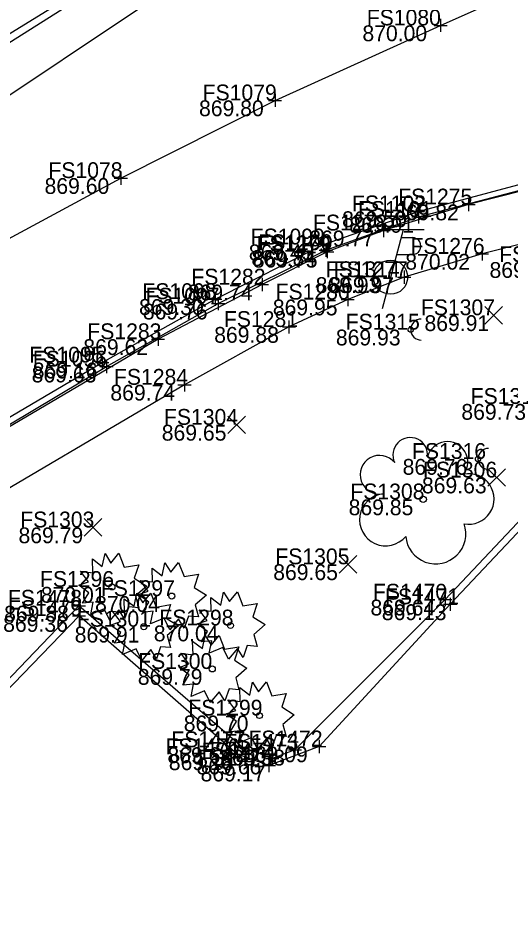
# Model space of a CAD drawing. Extents: x 1479420 to 1479833, y 379731 to 380103.
# Drawn here: x 1479485.7 to 1479523.1, y 379796.9 to 379864.3 of the extents above; entities that cross this region are included whole.
import ezdxf

# ---------------------------------------------------------------- set-up
doc = ezdxf.new("R2010")
doc.units = 0
for name, color, linetype in [('PV_X_COP', 7, 'Continuous'), ('PV_X_Curb', 7, 'Continuous'), ('PV_X_Walk', 7, 'Continuous'), ('SV_X_Random_Point', 7, 'Continuous'), ('SV_X_Shot_Marker', 7, 'Continuous'), ('SV_X_Text_Elevation', 7, 'Continuous'), ('SV_X_Text_Name', 7, 'Continuous'), ('UT_X_Misc_Cells', 7, 'Continuous'), ('UT_X_Water', 7, 'Continuous'), ('VG_X_Cells', 7, 'Continuous')]:
    doc.layers.add(name, color=color, linetype=linetype)

msp = doc.modelspace()

# ---------------------------------------------------------------- linework, layer by layer
at = {"layer": 'PV_X_COP'}
msp.add_lwpolyline([(1479441.789, 379822.02), (1479455.003, 379829.684), (1479469.105, 379838.412), (1479482.144, 379845.998), (1479493.535, 379852.152), (1479505.235, 379858.045), (1479517.8, 379863.732), (1479530.742, 379869.52), (1479544.647, 379875.382), (1479558.927, 379881.46), (1479574.038, 379887.901), (1479589.196, 379894.596), (1479596.439, 379897.36)], dxfattribs=at)
at = {"layer": 'PV_X_Curb'}
for points in [[(1479566.948, 379909.055), (1479563.851, 379905.522), (1479559.694, 379902.148), (1479555.354, 379899.307), (1479545.42, 379894.598), (1479534.9, 379889.656), (1479522.397, 379883.596), (1479509.98, 379877.664), (1479501.207, 379872.624), (1479492.667, 379867.773), (1479483.86, 379862.333), (1479467.175, 379851.843), (1479450.132, 379841.187), (1479435.273, 379831.857)], [(1479567.166, 379908.643), (1479563.944, 379905.002), (1479559.953, 379901.759), (1479555.611, 379898.812), (1479545.712, 379894.104), (1479535.142, 379889.114), (1479522.804, 379883.209), (1479510.321, 379877.208), (1479501.52, 379872.223), (1479492.734, 379867.269), (1479484.26, 379861.901), (1479467.4, 379851.399), (1479450.552, 379840.846), (1479435.368, 379831.409)], [(1479448.263, 379811.446), (1479461.223, 379819.505), (1479478.3, 379830.094), (1479484.788, 379833.845), (1479492.119, 379838.16), (1479500.701, 379842.975), (1479508.918, 379847.117), (1479516.087, 379849.63), (1479529.031, 379853.073), (1479547.645, 379857.816), (1479566.743, 379862.68), (1479585.84, 379867.633), (1479595.941, 379870.21)], [(1479448.497, 379810.926), (1479461.699, 379819.081), (1479478.683, 379829.765), (1479485.034, 379833.446), (1479492.452, 379837.857), (1479500.924, 379842.633), (1479509.095, 379846.687), (1479516.116, 379849.207), (1479529.309, 379852.683), (1479547.62, 379857.329), (1479567.188, 379862.296), (1479585.958, 379867.104), (1479596.074, 379869.8)], [(1479601.319, 379856.891), (1479590.521, 379858.038), (1479580.718, 379858.057), (1479571.147, 379856.791), (1479561.287, 379853.753), (1479553.092, 379850.702), (1479544.73, 379845.631), (1479537.421, 379839.852), (1479530.35, 379833.145), (1479518.148, 379820.183), (1479506.748, 379808.804), (1479505.037, 379808.132), (1479502.743, 379808.986), (1479490.356, 379819.723), (1479452.909, 379780.6)], [(1479601.347, 379856.369), (1479590.364, 379857.442), (1479580.925, 379857.48), (1479571.059, 379856.275), (1479561.558, 379853.273), (1479553.285, 379850.192), (1479545.205, 379845.234), (1479537.871, 379839.395), (1479530.786, 379832.841), (1479518.522, 379819.829), (1479508.592, 379809.053), (1479504.774, 379807.6), (1479502.376, 379808.454), (1479490.367, 379818.943), (1479453.507, 379780.799)]]:
    msp.add_lwpolyline(points, dxfattribs=at)
at = {"layer": 'PV_X_Walk'}
for points in [[(1479600.533, 379870.638), (1479580.734, 379865.6), (1479561.549, 379860.766), (1479542.709, 379855.919), (1479519.925, 379850.15), (1479513.475, 379848.178), (1479509.191, 379846.567), (1479504.249, 379844.075), (1479496.362, 379839.934), (1479478.251, 379829.275), (1479450.128, 379811.818)], [(1479601.313, 379866.859), (1479581.547, 379861.918), (1479562.5, 379857.02), (1479543.703, 379852.153), (1479520.939, 379846.407), (1479515.035, 379844.633), (1479510.748, 379842.941), (1479506.291, 379840.861), (1479498.375, 379836.477), (1479480.408, 379825.918), (1479452.204, 379808.527)]]:
    msp.add_lwpolyline(points, dxfattribs=at)
at = {"layer": 'SV_X_Random_Point'}
for p, q in [((1479521.152, 379841.083), (1479522.486, 379842.418)), ((1479521.152, 379842.418), (1479522.486, 379841.083)), ((1479501.654, 379832.774), (1479502.988, 379834.109)), ((1479501.654, 379834.109), (1479502.988, 379832.774)), ((1479521.393, 379828.776), (1479522.727, 379830.111)), ((1479521.393, 379830.111), (1479522.727, 379828.776)), ((1479490.759, 379824.993), (1479492.093, 379826.328)), ((1479490.759, 379826.328), (1479492.093, 379824.993)), ((1479510.111, 379822.197), (1479511.445, 379823.532)), ((1479510.111, 379823.532), (1479511.445, 379822.197))]:
    msp.add_line(p, q, dxfattribs=at)
at = {"layer": 'SV_X_Shot_Marker'}
for p, q in [((1479517.3, 379863.732), (1479518.3, 379863.732)), ((1479517.8, 379864.232), (1479517.8, 379863.232)), ((1479517.8, 379863.732), (1479517.8, 379863.732)), ((1479505.235, 379858.545), (1479505.235, 379857.545)), ((1479504.735, 379858.045), (1479505.735, 379858.045)), ((1479505.235, 379858.045), (1479505.235, 379858.045)), ((1479493.535, 379852.652), (1479493.535, 379851.652)), ((1479493.035, 379852.152), (1479494.035, 379852.152)), ((1479493.535, 379852.152), (1479493.535, 379852.152)), ((1479519.925, 379850.65), (1479519.925, 379849.65)), ((1479515.587, 379849.63), (1479516.587, 379849.63)), ((1479516.087, 379850.13), (1479516.087, 379849.13)), ((1479516.087, 379849.63), (1479516.087, 379849.63)), ((1479516.116, 379849.707), (1479516.116, 379848.707)), ((1479519.425, 379850.15), (1479520.425, 379850.15)), ((1479519.925, 379850.15), (1479519.925, 379850.15)), ((1479515.616, 379849.207), (1479516.616, 379849.207)), ((1479516.116, 379849.207), (1479516.116, 379849.207)), ((1479513.475, 379848.678), (1479513.475, 379847.678)), ((1479508.918, 379847.617), (1479508.918, 379846.617)), ((1479512.975, 379848.178), (1479513.975, 379848.178)), ((1479513.475, 379848.178), (1479513.475, 379848.178)), ((1479508.418, 379847.117), (1479509.418, 379847.117)), ((1479508.918, 379847.117), (1479508.918, 379847.117)), ((1479509.095, 379847.187), (1479509.095, 379846.187)), ((1479509.191, 379847.067), (1479509.191, 379846.067)), ((1479520.939, 379846.907), (1479520.939, 379845.907)), ((1479508.595, 379846.687), (1479509.595, 379846.687)), ((1479508.691, 379846.567), (1479509.691, 379846.567)), ((1479509.095, 379846.687), (1479509.095, 379846.687)), ((1479509.191, 379846.567), (1479509.191, 379846.567)), ((1479520.439, 379846.407), (1479521.439, 379846.407)), ((1479520.939, 379846.407), (1479520.939, 379846.407)), ((1479515.035, 379845.133), (1479515.035, 379844.133)), ((1479504.249, 379844.575), (1479504.249, 379843.575)), ((1479514.535, 379844.633), (1479515.535, 379844.633)), ((1479515.035, 379844.633), (1479515.035, 379844.633)), ((1479500.701, 379843.475), (1479500.701, 379842.475)), ((1479503.749, 379844.075), (1479504.749, 379844.075)), ((1479504.249, 379844.075), (1479504.249, 379844.075)), ((1479500.201, 379842.975), (1479501.201, 379842.975)), ((1479500.701, 379842.975), (1479500.701, 379842.975)), ((1479500.924, 379843.133), (1479500.924, 379842.133)), ((1479510.248, 379842.941), (1479511.248, 379842.941)), ((1479510.748, 379843.441), (1479510.748, 379842.441)), ((1479510.748, 379842.941), (1479510.748, 379842.941)), ((1479500.424, 379842.633), (1479501.424, 379842.633)), ((1479500.924, 379842.633), (1479500.924, 379842.633)), ((1479505.791, 379840.861), (1479506.791, 379840.861)), ((1479506.291, 379841.361), (1479506.291, 379840.361)), ((1479506.291, 379840.861), (1479506.291, 379840.861)), ((1479496.362, 379840.434), (1479496.362, 379839.434)), ((1479495.862, 379839.934), (1479496.862, 379839.934)), ((1479496.362, 379839.934), (1479496.362, 379839.934)), ((1479491.619, 379838.16), (1479492.619, 379838.16)), ((1479492.119, 379838.66), (1479492.119, 379837.66)), ((1479492.119, 379838.16), (1479492.119, 379838.16)), ((1479492.452, 379838.357), (1479492.452, 379837.357)), ((1479491.952, 379837.857), (1479492.952, 379837.857)), ((1479492.452, 379837.857), (1479492.452, 379837.857)), ((1479498.375, 379836.977), (1479498.375, 379835.977)), ((1479497.875, 379836.477), (1479498.875, 379836.477)), ((1479498.375, 379836.477), (1479498.375, 379836.477)), ((1479518.148, 379820.683), (1479518.148, 379819.683)), ((1479490.356, 379820.223), (1479490.356, 379819.223)), ((1479517.648, 379820.183), (1479518.648, 379820.183)), ((1479518.148, 379820.183), (1479518.148, 379820.183)), ((1479518.522, 379820.329), (1479518.522, 379819.329)), ((1479489.856, 379819.723), (1479490.856, 379819.723)), ((1479490.356, 379819.723), (1479490.356, 379819.723)), ((1479490.367, 379819.443), (1479490.367, 379818.443)), ((1479518.022, 379819.829), (1479519.022, 379819.829)), ((1479518.522, 379819.829), (1479518.522, 379819.829)), ((1479489.867, 379818.943), (1479490.867, 379818.943)), ((1479490.367, 379818.943), (1479490.367, 379818.943)), ((1479502.743, 379809.486), (1479502.743, 379808.486)), ((1479506.748, 379809.304), (1479506.748, 379808.304)), ((1479508.592, 379809.553), (1479508.592, 379808.553)), ((1479501.876, 379808.454), (1479502.876, 379808.454)), ((1479502.243, 379808.986), (1479503.243, 379808.986)), ((1479502.376, 379808.954), (1479502.376, 379807.954)), ((1479502.376, 379808.454), (1479502.376, 379808.454)), ((1479502.743, 379808.986), (1479502.743, 379808.986)), ((1479505.037, 379808.632), (1479505.037, 379807.632)), ((1479506.248, 379808.804), (1479507.248, 379808.804)), ((1479506.748, 379808.804), (1479506.748, 379808.804)), ((1479508.092, 379809.053), (1479509.092, 379809.053)), ((1479508.592, 379809.053), (1479508.592, 379809.053)), ((1479504.537, 379808.132), (1479505.537, 379808.132)), ((1479504.774, 379808.1), (1479504.774, 379807.1)), ((1479505.037, 379808.132), (1479505.037, 379808.132)), ((1479504.274, 379807.6), (1479505.274, 379807.6)), ((1479504.774, 379807.6), (1479504.774, 379807.6))]:
    msp.add_line(p, q, dxfattribs=at)
at = {"layer": 'UT_X_Misc_Cells'}
for p, q in [((1479514.963, 379848.237), (1479513.357, 379842.237)), ((1479516.563, 379848.237), (1479513.363, 379848.237)), ((1479514.803, 379847.637), (1479515.653, 379847.637)), ((1479514.462, 379846.362), (1479515.653, 379846.362))]:
    msp.add_line(p, q, dxfattribs=at)
for centre, radius in [((1479514, 379844.637), 1.3), ((1479515.532, 379840.661), 0.2), ((1479520.633, 379830.853), 0.2)]:
    msp.add_circle(centre, radius, dxfattribs=at)
for centre, radius, start, end in [((1479515.666, 379847), 0.638, 268.8767, 91.1233), ((1479516.332, 379840.661), 0.8, 90, 270), ((1479521.433, 379830.853), 0.8, 90, 270)]:
    msp.add_arc(centre, radius, start, end, dxfattribs=at)
at = {"layer": 'UT_X_Water'}
msp.add_lwpolyline([(1479451.52, 379837.183), (1479469.615, 379848.275), (1479481.983, 379856.402), (1479496.242, 379865.929), (1479520, 379881.305), (1479538.557, 379892.999), (1479553.442, 379903.409), (1479554.944, 379904.326), (1479564.844, 379911.311), (1479573.24, 379917.005), (1479582.403, 379926.468), (1479585.515, 379929.786), (1479589.646, 379934.736), (1479591.405, 379936.451), (1479593.775, 379939.334)], dxfattribs=at)
at = {"layer": 'VG_X_Cells'}
for points in [[(1479492.782, 379822.96), (1479493.387, 379823.695), (1479493.802, 379822.642), (1479494.894, 379822.822), (1479494.555, 379821.81), (1479495.5, 379821.215), (1479494.644, 379820.48), (1479494.894, 379819.567), (1479494.14, 379819.635), (1479493.815, 379818.722), (1479493.387, 379819.414), (1479492.709, 379818.597), (1479492.28, 379819.484), (1479491.26, 379819.054), (1479491.452, 379819.995), (1479490.64, 379819.912), (1479491.114, 379820.702), (1479490.345, 379821.27), (1479491.084, 379821.534), (1479490.477, 379822.337), (1479491.409, 379822.227), (1479491.379, 379823.265), (1479492.132, 379822.697), (1479492.339, 379823.682), (1479492.782, 379822.96)], [(1479497.321, 379822.262), (1479497.926, 379822.997), (1479498.341, 379821.944), (1479499.433, 379822.124), (1479499.094, 379821.112), (1479500.039, 379820.517), (1479499.183, 379819.782), (1479499.433, 379818.869), (1479498.679, 379818.937), (1479498.354, 379818.024), (1479497.926, 379818.715), (1479497.248, 379817.899), (1479496.819, 379818.785), (1479495.799, 379818.355), (1479495.991, 379819.297), (1479495.179, 379819.214), (1479495.653, 379820.004), (1479494.884, 379820.572), (1479495.623, 379820.835), (1479495.016, 379821.639), (1479495.948, 379821.529), (1479495.918, 379822.567), (1479496.671, 379821.999), (1479496.878, 379822.984), (1479497.321, 379822.262)], [(1479495.199, 379819.94), (1479495.804, 379820.675), (1479496.219, 379819.622), (1479497.311, 379819.802), (1479496.972, 379818.79), (1479497.917, 379818.195), (1479497.061, 379817.46), (1479497.311, 379816.547), (1479496.557, 379816.615), (1479496.232, 379815.702), (1479495.804, 379816.394), (1479495.126, 379815.577), (1479494.697, 379816.464), (1479493.677, 379816.034), (1479493.869, 379816.975), (1479493.057, 379816.892), (1479493.531, 379817.682), (1479492.762, 379818.25), (1479493.501, 379818.514), (1479492.894, 379819.317), (1479493.826, 379819.207), (1479493.796, 379820.245), (1479494.549, 379819.677), (1479494.756, 379820.662), (1479495.199, 379819.94)], [(1479501.774, 379820.032), (1479502.379, 379820.767), (1479502.794, 379819.714), (1479503.886, 379819.894), (1479503.547, 379818.882), (1479504.492, 379818.287), (1479503.636, 379817.552), (1479503.886, 379816.639), (1479503.132, 379816.707), (1479502.807, 379815.794), (1479502.379, 379816.486), (1479501.701, 379815.669), (1479501.272, 379816.556), (1479500.252, 379816.126), (1479500.444, 379817.067), (1479499.632, 379816.984), (1479500.106, 379817.774), (1479499.337, 379818.342), (1479500.076, 379818.606), (1479499.469, 379819.409), (1479500.401, 379819.299), (1479500.371, 379820.337), (1479501.124, 379819.769), (1479501.331, 379820.754), (1479501.774, 379820.032)], [(1479500.391, 379816.736), (1479500.996, 379817.471), (1479501.411, 379816.418), (1479502.503, 379816.598), (1479502.164, 379815.586), (1479503.109, 379814.991), (1479502.253, 379814.256), (1479502.503, 379813.343), (1479501.749, 379813.411), (1479501.424, 379812.498), (1479500.996, 379813.189), (1479500.318, 379812.373), (1479499.889, 379813.259), (1479498.869, 379812.829), (1479499.061, 379813.771), (1479498.249, 379813.688), (1479498.723, 379814.478), (1479497.954, 379815.046), (1479498.693, 379815.309), (1479498.086, 379816.113), (1479499.018, 379816.003), (1479498.988, 379817.041), (1479499.741, 379816.473), (1479499.948, 379817.458), (1479500.391, 379816.736)], [(1479503.973, 379813.204), (1479504.578, 379813.939), (1479504.993, 379812.885), (1479506.085, 379813.065), (1479505.746, 379812.054), (1479506.691, 379811.459), (1479505.835, 379810.724), (1479506.085, 379809.81), (1479505.331, 379809.879), (1479505.006, 379808.965), (1479504.578, 379809.657), (1479503.9, 379808.84), (1479503.471, 379809.727), (1479502.451, 379809.297), (1479502.643, 379810.239), (1479501.831, 379810.155), (1479502.305, 379810.945), (1479501.536, 379811.514), (1479502.275, 379811.777), (1479501.668, 379812.58), (1479502.6, 379812.47), (1479502.57, 379813.509), (1479503.323, 379812.94), (1479503.53, 379813.925), (1479503.973, 379813.204)]]:
    msp.add_lwpolyline(points, dxfattribs=at)
for centre, radius in [((1479516.48, 379827.785), 0.24), ((1479492.866, 379821.151), 0.23), ((1479497.405, 379820.452), 0.23), ((1479495.283, 379818.131), 0.23), ((1479501.858, 379818.223), 0.23), ((1479500.475, 379814.926), 0.23), ((1479504.057, 379811.394), 0.23)]:
    msp.add_circle(centre, radius, dxfattribs=at)
for centre, radius, start, end in [((1479515.496, 379831.153), 1.317, 354.0047, 205.97412), ((1479518.306, 379830.614), 1.553, 323.82996, 165.0376), ((1479513.171, 379829.649), 1.471, 39.06254, 279.54124), ((1479519.94, 379827.821), 1.915, 259.14531, 101.45961), ((1479513.627, 379826.236), 1.974, 96.17219, 320.57371), ((1479517.426, 379825.18), 2.284, 184.94757, 19.45715)]:
    msp.add_arc(centre, radius, start, end, dxfattribs=at)

# ---------------------------------------------------------------- texts
at = {"layer": 'SV_X_Text_Elevation'}
for s, p in [('870.00', (1479511.867, 379862.532)), ('869.80', (1479499.472, 379856.845)), ('869.60', (1479487.753, 379850.952)), ('869.50', (1479510.324, 379848.43)), ('869.82', (1479514.275, 379848.95)), ('869.91', (1479510.871, 379848.007)), ('869.77', (1479507.834, 379846.978)), ('869.45', (1479503.249, 379845.917)), ('869.84', (1479503.445, 379845.487)), ('869.75', (1479503.55, 379845.367)), ('870.02', (1479515.119, 379845.207)), ('869.84', (1479521.509, 379844.583)), ('869.93', (1479508.322, 379843.437)), ('869.97', (1479509.357, 379843.433)), ('869.74', (1479498.618, 379842.875)), ('869.30', (1479494.919, 379841.775)), ('869.95', (1479505.07, 379841.741)), ('869.76', (1479495.208, 379841.433)), ('869.91', (1479516.574, 379840.551)), ('869.88', (1479500.622, 379839.661)), ('869.93', (1479509.854, 379839.461)), ('869.62', (1479490.693, 379838.734)), ('869.16', (1479486.857, 379836.96)), ('869.63', (1479486.774, 379836.657)), ('869.74', (1479492.744, 379835.277)), ('869.73', (1479519.372, 379833.823)), ('869.65', (1479496.643, 379832.241)), ('869.76', (1479514.917, 379829.653)), ('869.63', (1479516.382, 379828.244)), ('869.85', (1479510.821, 379826.585)), ('869.79', (1479485.776, 379824.461)), ('869.65', (1479505.1, 379821.664)), ('870.01', (1479487.471, 379819.95)), ('870.04', (1479491.586, 379819.252)), ('869.64', (1479512.479, 379818.983)), ('869.88', (1479484.687, 379818.523)), ('869.13', (1479513.336, 379818.629)), ('869.36', (1479484.613, 379817.743)), ('869.91', (1479490.039, 379816.93)), ('870.04', (1479496.039, 379817.022)), ('869.79', (1479494.826, 379813.726)), ('869.70', (1479498.313, 379810.194)), ('869.09', (1479502.81, 379807.853)), ('869.64', (1479497.074, 379807.786)), ('869.18', (1479497.18, 379807.254)), ('869.58', (1479501.079, 379807.604)), ('869.66', (1479499.283, 379806.932)), ('869.17', (1479499.588, 379806.4))]:
    msp.add_text(s, height=1.2, dxfattribs=at).set_placement(p)
at = {"layer": 'SV_X_Text_Name'}
for s, p in [('FS1080', (1479512.198, 379863.732)), ('FS1079', (1479499.746, 379858.045)), ('FS1078', (1479488.046, 379852.152)), ('FS1275', (1479514.578, 379850.15)), ('FS1102', (1479511.071, 379849.63)), ('FS1101', (1479511.525, 379849.207)), ('FS1278', (1479508.119, 379848.178)), ('FS1099', (1479503.391, 379847.117)), ('FS1279', (1479503.835, 379846.567)), ('FS1100', (1479503.966, 379846.687)), ('FS1276', (1479515.516, 379846.407)), ('FS1312', (1479522.238, 379845.783)), ('FS1314', (1479509.079, 379844.637)), ('FS1277', (1479509.688, 379844.633)), ('FS1282', (1479498.893, 379844.075)), ('FS1098', (1479495.174, 379842.975)), ('FS1280', (1479505.278, 379842.941)), ('FS1097', (1479495.407, 379842.633)), ('FS1307', (1479516.302, 379841.751)), ('FS1281', (1479501.359, 379840.861)), ('FS1315', (1479510.601, 379840.661)), ('FS1283', (1479490.996, 379839.934)), ('FS1095', (1479486.602, 379838.16)), ('FS1096', (1479486.859, 379837.857)), ('FS1284', (1479493.019, 379836.477)), ('FS1313', (1479520.082, 379835.023)), ('FS1304', (1479496.813, 379833.441)), ('FS1316', (1479515.627, 379830.853)), ('FS1306', (1479516.467, 379829.444)), ('FS1308', (1479510.953, 379827.785)), ('FS1303', (1479485.909, 379825.661)), ('FS1305', (1479505.261, 379822.864)), ('FS1296', (1479487.407, 379821.15)), ('FS1297', (1479492.021, 379820.452)), ('FS1470', (1479512.669, 379820.183)), ('FS1478', (1479484.971, 379819.723)), ('FS1471', (1479513.581, 379819.829)), ('FS1479', (1479484.982, 379818.943)), ('FS1301', (1479490.201, 379818.13)), ('FS1298', (1479496.465, 379818.222)), ('FS1300', (1479494.855, 379814.926)), ('FS1299', (1479498.664, 379811.394)), ('FS1477', (1479497.368, 379808.986)), ('FS1473', (1479501.373, 379808.804)), ('FS1472', (1479503.226, 379809.053)), ('FS1476', (1479496.925, 379808.454)), ('FS1474', (1479499.671, 379808.132)), ('FS1475', (1479499.399, 379807.6))]:
    msp.add_text(s, height=1.2, dxfattribs=at).set_placement(p)

doc.saveas('drawing.dxf')
